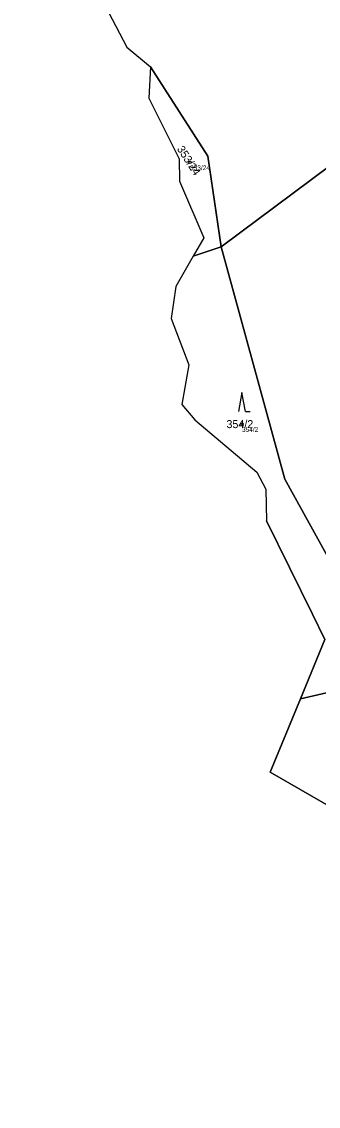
# Model space of a CAD drawing. Extents: x -700238 to -698499, y -1070626 to -1068006.
# Drawn here: x -699925.2 to -699862.2, y -1070538.6 to -1070308.3 of the extents above; entities that cross this region are included whole.
import ezdxf

# ---------------------------------------------------------------- set-up
doc = ezdxf.new("R2010")
doc.units = 0
for name, color, linetype in [('Definiční body', 7, 'Continuous'), ('Hranice parcel', 7, 'Continuous'), ('Parcelní čísla', 7, 'Continuous'), ('Polygon ku', 7, 'Continuous'), ('Polygon parcely', 7, 'Continuous'), ('Značky kultur', 7, 'Continuous')]:
    doc.layers.add(name, color=color, linetype=linetype)

msp = doc.modelspace()

# ---------------------------------------------------------------- linework, layer by layer
at = {"layer": 'Definiční body'}
for centre in [(-699889.46, -1070338.13994), (-699878.43, -1070393.72994)]:
    msp.add_circle(centre, 0.25, dxfattribs=at)
at = {"layer": 'Hranice parcel'}
for p, q in [((-699908.34, -1070303.23), (-699902.91, -1070313.7)), ((-699902.91, -1070313.7), (-699897.86, -1070317.82)), ((-699829.22, -1070316.05), (-699882.86, -1070356.11)), ((-699897.86, -1070317.82), (-699898.21, -1070324.48)), ((-699898.21, -1070324.48), (-699891.78, -1070337.37)), ((-699891.78, -1070337.37), (-699891.69, -1070342.16)), ((-699891.69, -1070342.16), (-699886.53, -1070354.18)), ((-699886.53, -1070354.18), (-699888.79, -1070358.09)), ((-699888.79, -1070358.09), (-699882.86, -1070356.11)), ((-699888.79, -1070358.09), (-699892.49, -1070364.5)), ((-699892.49, -1070364.5), (-699893.45, -1070371.29)), ((-699893.45, -1070371.29), (-699889.73, -1070381.16)), ((-699888.47, -1070392.83), (-699875.28, -1070403.97)), ((-699863.46, -1070434.09), (-699873.23, -1070414.3)), ((-699852.48, -1070448.98), (-699865.99, -1070452.05)), ((-699872.42, -1070467.67), (-699865.99, -1070452.05))]:
    msp.add_line(p, q, dxfattribs=at)
for points in [[(-699882.86, -1070356.11), (-699885.7, -1070336.85), (-699897.86, -1070317.82)], [(-699882.86, -1070356.11), (-699869.32, -1070405.39), (-699853.83, -1070433.45), (-699852.48, -1070448.98)], [(-699889.73, -1070381.16), (-699891.17, -1070389.56), (-699888.47, -1070392.83)], [(-699875.28, -1070403.97), (-699873.4, -1070407.52), (-699873.23, -1070414.3)], [(-699865.99, -1070452.05), (-699860.81, -1070439.46), (-699863.46, -1070434.09)], [(-699819.65, -1070526.5), (-699841.74, -1070485.33), (-699872.42, -1070467.67)]]:
    msp.add_lwpolyline(points, dxfattribs=at)
at = {"layer": 'Polygon ku'}
msp.add_lwpolyline([(-699908.34, -1070303.23), (-699902.91, -1070313.7), (-699897.86, -1070317.82), (-699898.21, -1070324.48), (-699891.78, -1070337.37), (-699891.69, -1070342.16), (-699886.53, -1070354.18), (-699888.79, -1070358.09), (-699892.49, -1070364.5), (-699893.45, -1070371.29), (-699889.73, -1070381.16), (-699891.17, -1070389.56), (-699888.47, -1070392.83), (-699875.28, -1070403.97), (-699873.4, -1070407.52), (-699873.23, -1070414.3), (-699863.46, -1070434.09), (-699860.81, -1070439.46), (-699865.99, -1070452.05), (-699872.42, -1070467.67), (-699841.74, -1070485.33)], dxfattribs=at)
at = {"layer": 'Polygon parcely'}
for points in [[(-699908.34, -1070303.23), (-699902.91, -1070313.7), (-699897.86, -1070317.82), (-699885.7, -1070336.85), (-699882.86, -1070356.11), (-699829.22, -1070316.05), (-699881.39, -1070243.41), (-699907.2, -1070262.01), (-699925.21, -1070275.42), (-699911.78, -1070295.95)], [(-699852.48, -1070448.98), (-699823.69, -1070482.27), (-699748.23, -1070428.52), (-699829.22, -1070316.05), (-699882.86, -1070356.11), (-699869.32, -1070405.39), (-699853.83, -1070433.45)], [(-699888.79, -1070358.09), (-699882.86, -1070356.11), (-699885.7, -1070336.85), (-699897.86, -1070317.82), (-699898.21, -1070324.48), (-699891.78, -1070337.37), (-699891.69, -1070342.16), (-699886.53, -1070354.18)], [(-699873.23, -1070414.3), (-699863.46, -1070434.09), (-699860.81, -1070439.46), (-699865.99, -1070452.05), (-699852.48, -1070448.98), (-699853.83, -1070433.45), (-699869.32, -1070405.39), (-699882.86, -1070356.11), (-699888.79, -1070358.09), (-699892.49, -1070364.5), (-699893.45, -1070371.29), (-699889.73, -1070381.16), (-699891.17, -1070389.56), (-699888.47, -1070392.83), (-699875.28, -1070403.97), (-699873.4, -1070407.52)], [(-699797.94, -1070511.03), (-699822, -1070484.36), (-699823.69, -1070482.27), (-699852.48, -1070448.98), (-699865.99, -1070452.05), (-699872.42, -1070467.67), (-699841.74, -1070485.33), (-699819.65, -1070526.5), (-699824.41, -1070538.61)]]:
    msp.add_lwpolyline(points, close=True, dxfattribs=at)
at = {"layer": 'Značky kultur'}
for p, q in [((-699878.43, -1070387.03), (-699879.18, -1070391.03)), ((-699877.68, -1070391.03), (-699878.43, -1070387.03)), ((-699877.68, -1070391.03), (-699876.684, -1070391.03))]:
    msp.add_line(p, q, dxfattribs=at)

# ---------------------------------------------------------------- texts
at = {"layer": 'Definiční body'}
for s, p in [('353/24', (-699889.46, -1070339.796)), ('354/2', (-699878.43, -1070395.386))]:
    msp.add_text(s, height=0.999996, dxfattribs=at).set_placement(p)
at = {"layer": 'Parcelní čísla'}
msp.add_text('353/24', height=1.699998, rotation=303, dxfattribs=at).set_placement((-699892.322, -1070335.292))
msp.add_text('354/2', height=1.699998, dxfattribs=at).set_placement((-699881.728, -1070394.58))

doc.saveas('drawing.dxf')
